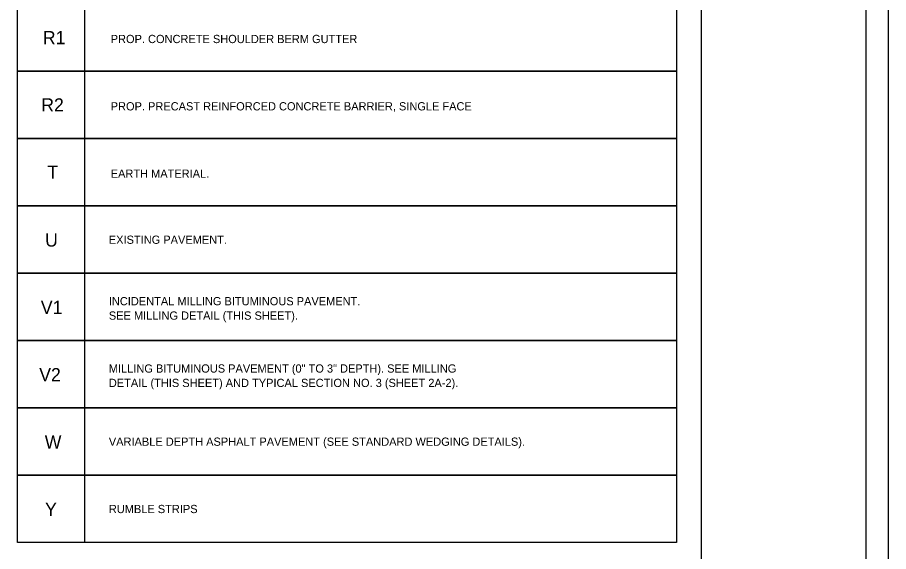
# Model space of a CAD drawing. Extents: x 1553884 to 1554215, y 810431 to 810779.
# Drawn here: x 1554077 to 1554156.4, y 810649.8 to 810698.5 of the extents above; entities that cross this region are included whole.
import ezdxf

# ---------------------------------------------------------------- set-up
doc = ezdxf.new("R2010")
doc.units = 0
for name, color, linetype in [('Old_Level_2', 7, 'Continuous'), ('Prop Dimension', 7, 'Continuous'), ('Prop Lane Arrow CELL', 7, 'Continuous')]:
    doc.layers.add(name, color=color, linetype=linetype)

msp = doc.modelspace()

# ---------------------------------------------------------------- linework, layer by layer
at = {"layer": 'Old_Level_2'}
for p, q in [((1554139.321, 810617.805), (1554139.325, 810776.052)), ((1554154.321, 810617.805), (1554154.325, 810776.052))]:
    msp.add_line(p, q, dxfattribs=at)
at = {"layer": 'Prop Dimension'}
msp.add_line((1554077.027, 810650.655), (1554077.027, 810650.655), dxfattribs=at)
for points in [[(1554083.164, 810693.609), (1554077.027, 810693.609), (1554077.027, 810699.745), (1554137.027, 810699.745), (1554137.027, 810693.609), (1554083.164, 810693.609), (1554083.164, 810699.745)], [(1554083.164, 810687.473), (1554077.027, 810687.473), (1554077.027, 810693.609), (1554137.027, 810693.609), (1554137.027, 810687.473), (1554083.164, 810687.473), (1554083.164, 810693.609)], [(1554083.164, 810681.337), (1554077.027, 810681.337), (1554077.027, 810687.473), (1554137.027, 810687.473), (1554137.027, 810681.337), (1554083.164, 810681.337), (1554083.164, 810687.473)], [(1554083.164, 810675.2), (1554077.027, 810675.2), (1554077.027, 810681.337), (1554137.027, 810681.337), (1554137.027, 810675.2), (1554083.164, 810675.2), (1554083.164, 810681.337)], [(1554083.164, 810669.064), (1554077.027, 810669.064), (1554077.027, 810675.2), (1554137.027, 810675.2), (1554137.027, 810669.064), (1554083.164, 810669.064), (1554083.164, 810675.2)], [(1554083.164, 810662.928), (1554077.027, 810662.928), (1554077.027, 810669.064), (1554137.027, 810669.064), (1554137.027, 810662.928), (1554083.164, 810662.928), (1554083.164, 810669.064)], [(1554083.164, 810656.792), (1554077.027, 810656.792), (1554077.027, 810662.928), (1554137.027, 810662.928), (1554137.027, 810656.792), (1554083.164, 810656.792), (1554083.164, 810662.928)], [(1554083.164, 810650.655), (1554077.027, 810650.655), (1554077.027, 810656.792), (1554137.027, 810656.792), (1554137.027, 810650.655), (1554083.164, 810650.655), (1554083.164, 810656.792)]]:
    msp.add_lwpolyline(points, dxfattribs=at)
at = {"layer": 'Prop Lane Arrow CELL'}
msp.add_line((1554156.35, 810614.43), (1554156.35, 810779.427), dxfattribs=at)

# ---------------------------------------------------------------- texts
at = {"layer": 'Prop Dimension'}
for s, height, p in [('R1', 1.2, (1554079.342, 810696.065)), ('PROP. CONCRETE SHOULDER BERM GUTTER', 0.75, (1554085.522, 810696.163)), ('R2', 1.2, (1554079.199, 810689.929)), ('PROP. PRECAST REINFORCED CONCRETE BARRIER, SINGLE FACE', 0.75, (1554085.522, 810690.027)), ('T', 1.2, (1554079.749, 810683.793)), ('EARTH MATERIAL.', 0.75, (1554085.522, 810683.89)), ('U', 1.2, (1554079.549, 810677.613)), ('EXISTING PAVEMENT.', 0.75, (1554085.351, 810677.868)), ('V1', 1.2, (1554079.158, 810671.477)), ('INCIDENTAL MILLING BITUMINOUS PAVEMENT.', 0.75, (1554085.351, 810672.264)), ('SEE MILLING DETAIL (THIS SHEET).', 0.75, (1554085.351, 810670.952)), ('V2', 1.2, (1554079.015, 810665.34)), ('MILLING BITUMINOUS PAVEMENT (0" TO 3" DEPTH). SEE MILLING ', 0.75, (1554085.351, 810666.128)), ('DETAIL (THIS SHEET) AND TYPICAL SECTION NO. 3 (SHEET 2A-2).', 0.75, (1554085.351, 810664.816)), ('W', 1.2, (1554079.518, 810659.204)), ('VARIABLE DEPTH ASPHALT PAVEMENT (SEE STANDARD WEDGING DETAILS).', 0.75, (1554085.351, 810659.459)), ('Y', 1.2, (1554079.544, 810653.068)), ('RUMBLE STRIPS', 0.75, (1554085.351, 810653.323))]:
    msp.add_text(s, height=height, dxfattribs=at).set_placement(p)

doc.saveas('drawing.dxf')
